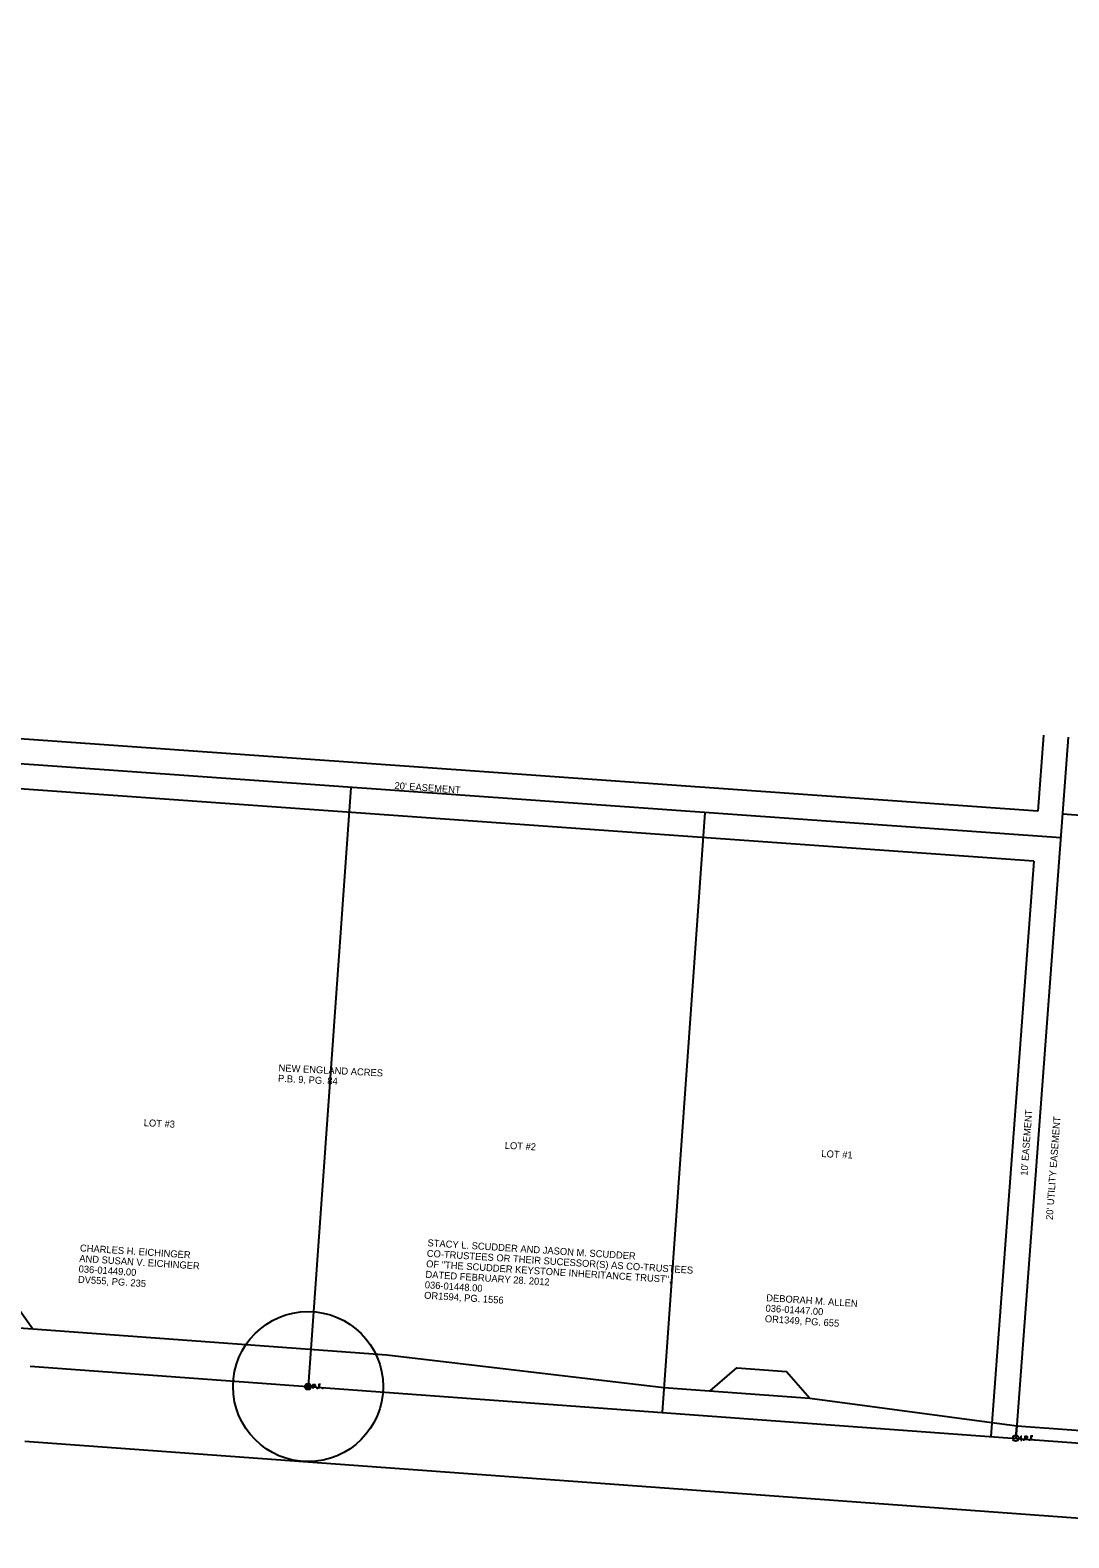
# Model space of a CAD drawing. Extents: x 1898254 to 1901377, y 701554 to 704886.
# Drawn here: x 1899818 to 1900233, y 703191 to 703794 of the extents above; entities that cross this region are included whole.
import ezdxf

# ---------------------------------------------------------------- set-up
doc = ezdxf.new("R2010")
doc.units = 0
for name, color, linetype in [('DV_X_Property_Line', 7, 'Continuous'), ('DV_X_Text', 7, 'Continuous'), ('RW_X_CL', 7, 'Continuous'), ('RW_X_Esmt_U', 7, 'Continuous'), ('RW_X_Fee_RW', 7, 'Continuous'), ('SC_Scratch1', 7, 'Continuous'), ('SC_Scratch2', 7, 'Continuous'), ('SV_P_Mon_Cells_Set', 7, 'Continuous'), ('SV_X_Mon_Cells_Found', 7, 'Continuous'), ('VG_P_Cells', 7, 'Continuous')]:
    doc.layers.add(name, color=color, linetype=linetype)

msp = doc.modelspace()

# ---------------------------------------------------------------- linework, layer by layer
at = {"layer": 'DV_X_Property_Line'}
for p, q in [((1900230.14, 703471.05), (1899662.55, 703511.42)), ((1900233.17, 703511.4), (1900212.15, 703230.94)), ((1899946.13, 703491.25), (1899929.09, 703251.63)), ((1900087.78, 703481.18), (1900070.72, 703241.28)), ((1900230.87, 703480.71), (1900642.66, 703450.49))]:
    msp.add_line(p, q, dxfattribs=at)
at = {"layer": 'RW_X_CL'}
msp.add_line((1899815.76, 703229.84), (1901162.17, 703131.42), dxfattribs=at)
at = {"layer": 'RW_X_Esmt_U'}
for p, q in [((1900220.92, 703481.74), (1899663.26, 703521.39)), ((1900223.2, 703512.15), (1900220.92, 703481.74)), ((1900219.42, 703461.79), (1899661.84, 703501.44)), ((1900219.42, 703461.79), (1900202.18, 703231.69))]:
    msp.add_line(p, q, dxfattribs=at)
at = {"layer": 'RW_X_Fee_RW'}
msp.add_line((1899817.95, 703259.76), (1900604.1, 703202.29), dxfattribs=at)
at = {"layer": 'SC_Scratch1'}
msp.add_circle((1899929.09, 703251.63), 30, dxfattribs=at)
at = {"layer": 'SC_Scratch2'}
msp.add_circle((1899815.76, 703229.84), 1561.35, dxfattribs=at)
at = {"layer": 'SV_P_Mon_Cells_Set'}
for points in [[(1899788.53, 703276.89), (1899789.24, 703286.86), (1899811.58, 703285.28), (1899819.04, 703274.72)], [(1900089.85, 703249.91), (1900100.56, 703259.15), (1900120.5, 703257.7), (1900129.75, 703246.99)], [(1900212.15, 703230.94), (1900212.52, 703235.93), (1900249.06, 703233.26), (1900279.35, 703236.06), (1900314.63, 703233.48), (1900328.85, 703227.43), (1900415.98, 703221.06), (1900415.61, 703216.07)]]:
    msp.add_lwpolyline(points, dxfattribs=at)
at = {"layer": 'SV_X_Mon_Cells_Found'}
for points in [[(1899931.09, 703250.83), (1899931.09, 703252.43), (1899931.62, 703252.43), (1899931.68, 703252.42), (1899931.75, 703252.4), (1899931.79, 703252.37), (1899931.82, 703252.35), (1899931.86, 703252.28), (1899931.9, 703252.22), (1899931.92, 703252.12), (1899931.92, 703251.97), (1899931.91, 703251.92), (1899931.89, 703251.84), (1899931.84, 703251.75), (1899931.8, 703251.72), (1899931.76, 703251.69), (1899931.71, 703251.67), (1899931.62, 703251.65), (1899931.09, 703251.65)], [(1899932.73, 703251.05), (1899932.79, 703251.05), (1899932.82, 703251.02), (1899932.86, 703250.97), (1899932.86, 703250.91), (1899932.82, 703250.86), (1899932.79, 703250.83), (1899932.73, 703250.83), (1899932.7, 703250.86), (1899932.67, 703250.91), (1899932.67, 703250.97), (1899932.7, 703251.02), (1899932.73, 703251.05)], [(1899934.1, 703252.43), (1899933.34, 703252.43), (1899933.34, 703250.83)], [(1899933.34, 703251.65), (1899933.88, 703251.65)], [(1899934.88, 703251.05), (1899934.94, 703251.05), (1899934.97, 703251.02), (1899935.01, 703250.97), (1899935.01, 703250.91), (1899934.97, 703250.86), (1899934.94, 703250.83), (1899934.88, 703250.83), (1899934.85, 703250.86), (1899934.82, 703250.91), (1899934.82, 703250.97), (1899934.85, 703251.02), (1899934.88, 703251.05)], [(1900214.17, 703231.77), (1900214.52, 703231.77)], [(1900214.17, 703230.17), (1900214.52, 703230.17)], [(1900214.34, 703230.17), (1900214.34, 703231.77)], [(1900215.3, 703230.38), (1900215.36, 703230.38), (1900215.39, 703230.36), (1900215.42, 703230.31), (1900215.42, 703230.24), (1900215.39, 703230.19), (1900215.36, 703230.17), (1900215.3, 703230.17), (1900215.27, 703230.19), (1900215.23, 703230.24), (1900215.23, 703230.31), (1900215.27, 703230.36), (1900215.3, 703230.38)], [(1900215.91, 703230.17), (1900215.91, 703231.77), (1900216.44, 703231.77), (1900216.49, 703231.75), (1900216.57, 703231.73), (1900216.6, 703231.7), (1900216.63, 703231.68), (1900216.68, 703231.62), (1900216.71, 703231.55), (1900216.73, 703231.45), (1900216.73, 703231.3), (1900216.72, 703231.25), (1900216.7, 703231.18), (1900216.66, 703231.09), (1900216.61, 703231.05), (1900216.58, 703231.02), (1900216.52, 703231), (1900216.44, 703230.99), (1900215.91, 703230.99)], [(1900217.55, 703230.38), (1900217.6, 703230.38), (1900217.64, 703230.36), (1900217.67, 703230.31), (1900217.67, 703230.24), (1900217.64, 703230.19), (1900217.6, 703230.17), (1900217.55, 703230.17), (1900217.52, 703230.19), (1900217.48, 703230.24), (1900217.48, 703230.31), (1900217.52, 703230.36), (1900217.55, 703230.38)], [(1900218.92, 703231.77), (1900218.16, 703231.77), (1900218.16, 703230.17)], [(1900218.16, 703230.99), (1900218.7, 703230.99)], [(1900219.7, 703230.38), (1900219.75, 703230.38), (1900219.79, 703230.36), (1900219.82, 703230.31), (1900219.82, 703230.24), (1900219.79, 703230.19), (1900219.75, 703230.17), (1900219.7, 703230.17), (1900219.67, 703230.19), (1900219.63, 703230.24), (1900219.63, 703230.31), (1900219.67, 703230.36), (1900219.7, 703230.38)]]:
    msp.add_lwpolyline(points, dxfattribs=at)
for centre, radius in [((1899929.09, 703251.63), 1.2), ((1899929.09, 703251.63), 0.495), ((1900212.15, 703230.97), 1.2)]:
    msp.add_circle(centre, radius, dxfattribs=at)
at = {"layer": 'VG_P_Cells'}
msp.add_lwpolyline([(1899647.24, 703291.95), (1899701.15, 703283.1), (1899819.04, 703274.72), (1899960.56, 703264.37), (1900071.43, 703251.26), (1900129.75, 703246.99), (1900212.52, 703235.93), (1900212.15, 703230.94)], dxfattribs=at)

# ---------------------------------------------------------------- texts
at = {"layer": 'DV_X_Property_Line'}
for s, p in [('CO-TRUSTEES OR THEIR SUCESSOR(S) AS CO-TRUSTEES ', (1899976.51, 703303.57)), ('STACY L. SCUDDER AND JASON M. SCUDDER ', (1899976.78, 703307.76)), ('OF "THE SCUDDER KEYSTONE INHERITANCE TRUST", ', (1899976.24, 703299.38)), ('036-01448.00', (1899975.71, 703290.99)), ('DATED FEBRUARY 28. 2012', (1899975.97, 703295.18)), ('OR1594, PG. 1556', (1899975.44, 703286.8))]:
    msp.add_text(s, height=2.8, rotation=356.3351, dxfattribs=at).set_placement(p)
at = {"layer": 'DV_X_Text'}
for s, rotation, p in [("20' EASEMENT ", 355.93252, (1899963.56, 703490.65)), ('NEW ENGLAND ACRES', 357.09486, (1899917.22, 703377.75)), ('P.B. 9, PG. 84', 357.09486, (1899917, 703373.55)), ("10' EASEMENT", 85.7139, (1900216.81, 703335.88)), ("20' UTILITY EASEMENT", 85.7139, (1900226.95, 703318.18)), ('LOT #3', 357.09486, (1899863.3, 703355.8)), ('LOT #2', 357.09486, (1900007.71, 703346.73)), ('LOT #1', 357.09486, (1900134.34, 703343.44)), ('CHARLES H. EICHINGER ', 356.3351, (1899837.77, 703305.72)), ('036-01449.00', 356.3351, (1899837.24, 703297.34)), ('AND SUSAN V. EICHINGER', 356.3351, (1899837.5, 703301.53)), ('DV555, PG. 235', 356.3351, (1899836.97, 703293.15)), ('DEBORAH M. ALLEN', 356.3351, (1900112.27, 703285.8)), ('036-01447.00', 356.3351, (1900112, 703281.61)), ('OR1349, PG. 655', 356.3351, (1900111.73, 703277.42))]:
    msp.add_text(s, height=2.8, rotation=rotation, dxfattribs=at).set_placement(p)

doc.saveas('drawing.dxf')
